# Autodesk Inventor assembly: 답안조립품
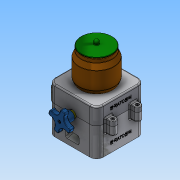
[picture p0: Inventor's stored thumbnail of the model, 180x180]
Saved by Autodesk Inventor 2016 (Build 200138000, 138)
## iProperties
Created: 2018-01
Part Number: 답안조립품
Material: 일반
Document SubType Name: Assembly
Designer: Administrator
Author: Administrator
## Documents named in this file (9)
- C:\Users\Administrator\Desktop\480107V1041\답안조립품.iam
- C:\Users\Administrator\Desktop\480107V1041\본체.ipt
- C:\Users\Administrator\Desktop\480107V1041\본체커버.ipt
- C:\Users\Administrator\Desktop\480107V1041\용기.ipt
- C:\Users\Administrator\Desktop\480107V1041\용기캡.ipt
- C:\Users\Administrator\Desktop\480107V1041\핸들.ipt
- C:\Users\Administrator\Desktop\480107V1041\핸들축.ipt
- C:\Users\Administrator\Desktop\480107V1041\볼트 M3x12.ipt
- C:\Users\Administrator\Desktop\480107V1041\볼트 M4x12.ipt
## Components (2 placed, 2 different names)
1. 핸들:1
2. 핸들축:1
